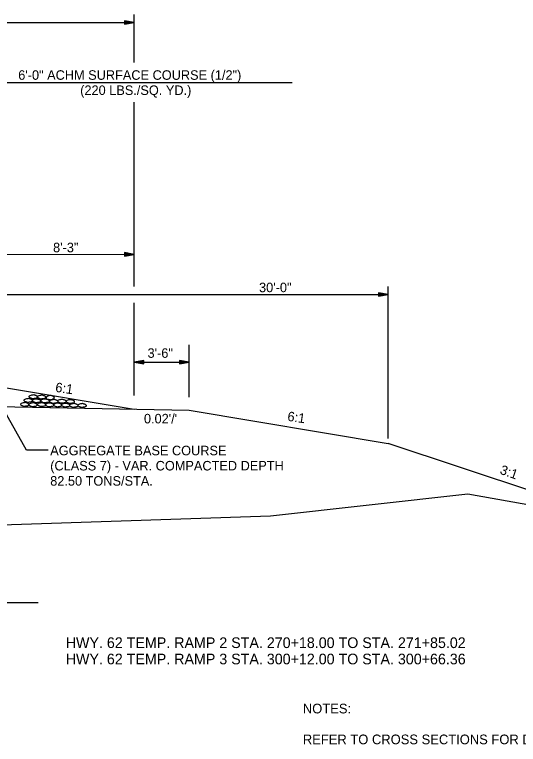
# Model space of a CAD drawing. Extents: x 1734743 to 1735935, y 759845 to 763831.
# Drawn here: x 1735771.91 to 1735803.12, y 759894.89 to 759940.09 of the extents above; entities that cross this region are included whole.
import ezdxf

# ---------------------------------------------------------------- set-up
doc = ezdxf.new("R2010")
doc.units = 0
for name, color, linetype in [('1', 7, 'Continuous'), ('19', 7, 'Continuous'), ('Level 1', 7, 'Continuous')]:
    doc.layers.add(name, color=color, linetype=linetype)

# ---------------------------------------------------------------- blocks, each defined once
blk = doc.blocks.new('ROCKS')
at = {"layer": '1'}
blk.add_spline([(0.013, 0.06), (0.053, 0.053), (0.107, 0.033), (0.133, 0.013), (0.133, -0.007), (0.12, -0.033), (0.107, -0.04), (0.073, -0.053), (0.033, -0.067), (0.013, -0.067), (-0.02, -0.06), (-0.06, -0.053), (-0.087, -0.047), (-0.113, -0.02), (-0.113, -0.007), (-0.107, 0.02), (-0.087, 0.033), (-0.067, 0.047), (-0.033, 0.053), (-0.02, 0.06), (0.013, 0.06)], degree=3, dxfattribs=at)

msp = doc.modelspace()

# ---------------------------------------------------------------- linework, layer by layer
at = {"layer": '19'}
for p, q in [((1735779.325, 759937.131), (1735779.325, 759940.095)), ((1735737.495, 759939.61), (1735779.325, 759939.61)), ((1735778.725, 759939.715), (1735778.725, 759939.505)), ((1735779.325, 759939.61), (1735778.725, 759939.715)), ((1735779.165, 759939.625), (1735778.725, 759939.66)), ((1735778.725, 759939.505), (1735779.325, 759939.61)), ((1735778.725, 759939.555), (1735779.165, 759939.595)), ((1735765.047, 759935.882), (1735789.111, 759935.882)), ((1735779.325, 759925.787), (1735779.325, 759934.676)), ((1735779.324, 759923.251), (1735779.325, 759925.787)), ((1735778.725, 759925.35), (1735778.725, 759925.14)), ((1735779.325, 759925.245), (1735778.725, 759925.35)), ((1735779.165, 759925.26), (1735778.725, 759925.295)), ((1735771.047, 759925.246), (1735779.325, 759925.245)), ((1735778.725, 759925.14), (1735779.325, 759925.245)), ((1735778.725, 759925.19), (1735779.165, 759925.23)), ((1735795.046, 759913.832), (1735795.046, 759923.252)), ((1735765.047, 759922.754), (1735795.046, 759922.754)), ((1735794.446, 759922.859), (1735794.446, 759922.649)), ((1735795.046, 759922.754), (1735794.446, 759922.859)), ((1735794.886, 759922.769), (1735794.446, 759922.804)), ((1735794.446, 759922.649), (1735795.046, 759922.754)), ((1735794.446, 759922.699), (1735794.886, 759922.739)), ((1735779.325, 759916.499), (1735779.325, 759922.252)), ((1735782.727, 759916.396), (1735782.727, 759919.643)), ((1735779.925, 759918.667), (1735779.325, 759918.562)), ((1735779.325, 759918.562), (1735782.727, 759918.562)), ((1735779.325, 759918.562), (1735779.925, 759918.457)), ((1735779.925, 759918.612), (1735779.485, 759918.577)), ((1735779.485, 759918.547), (1735779.925, 759918.507)), ((1735779.925, 759918.457), (1735779.925, 759918.667)), ((1735782.126, 759918.667), (1735782.126, 759918.457)), ((1735782.726, 759918.562), (1735782.126, 759918.667)), ((1735782.566, 759918.577), (1735782.126, 759918.612)), ((1735782.126, 759918.457), (1735782.726, 759918.562)), ((1735782.126, 759918.507), (1735782.566, 759918.547)), ((1735771.048, 759917.035), (1735779.325, 759915.655)), ((1735772.655, 759913.11), (1735770.742, 759916.503)), ((1735767.034, 759915.902), (1735782.728, 759915.586)), ((1735767.035, 759915.902), (1735782.727, 759915.587)), ((1735782.727, 759915.587), (1735795.046, 759913.532)), ((1735809.505, 759908.711), (1735795.046, 759913.532)), ((1735773.986, 759913.11), (1735772.655, 759913.11)), ((1735745.216, 759903.685), (1735773.379, 759903.682))]:
    msp.add_line(p, q, dxfattribs=at)
msp.add_lwpolyline([(1735737.574, 759909.405), (1735737.825, 759909.397), (1735746.995, 759910.076), (1735752.775, 759907.356), (1735767.375, 759908.375), (1735787.755, 759909.053), (1735799.985, 759910.412), (1735809.495, 759908.711), (1735820.81, 759911.149), (1735822.413, 759910.838)], dxfattribs=at)

# ---------------------------------------------------------------- block references
at = {"layer": 'Level 1'}
for p, xscale, yscale, rotation in [((1735772.773, 759916.204), 2.011654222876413, -2.011654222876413, 178.17361855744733), ((1735773.086, 759916.429), 2.011654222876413, -2.011654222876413, 178.17361855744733), ((1735773.291, 759916.181), 2.011654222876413, -2.011654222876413, 178.17361855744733), ((1735773.6, 759916.415), 2.011654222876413, -2.011654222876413, 178.17361855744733), ((1735773.82, 759916.177), 2.011654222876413, -2.011654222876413, 178.17361855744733), ((1735774.104, 759916.378), 2.0116542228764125, 2.0116542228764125, 0.9122903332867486), ((1735774.356, 759916.145), 2.011654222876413, -2.011654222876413, 178.17361855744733), ((1735774.862, 759916.152), 2.011654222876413, -2.011654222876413, 178.17361855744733), ((1735775.383, 759916.137), 2.011654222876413, -2.011654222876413, 178.17361855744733), ((1735772.557, 759915.955), 2.011654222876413, -2.011654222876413, 178.17361855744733), ((1735773.072, 759915.937), 2.011654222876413, -2.011654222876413, 178.17361855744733), ((1735773.611, 759915.946), 2.011654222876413, -2.011654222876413, 178.17361855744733), ((1735774.101, 759915.93), 2.011654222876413, -2.011654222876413, 178.17361855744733), ((1735774.598, 759915.923), 2.011654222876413, -2.011654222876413, 178.17361855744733), ((1735775.094, 759915.912), 2.011654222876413, -2.011654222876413, 178.17361855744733), ((1735775.594, 759915.898), 2.011654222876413, -2.011654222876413, 178.17361855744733), ((1735776.115, 759915.892), 2.011654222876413, -2.011654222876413, 178.17361855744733)]:
    msp.add_blockref('ROCKS', p, dxfattribs=dict(at, xscale=xscale, yscale=yscale, rotation=rotation))

# ---------------------------------------------------------------- texts
at = {"layer": '1'}
for s, p in [('NOTES:', (1735789.766, 759896.812)), ('REFER TO CROSS SECTIONS FOR DEVIATION FROM NORMAL SLOPES. NO CHANGES', (1735789.766, 759894.901))]:
    msp.add_text(s, height=0.6, dxfattribs=at).set_placement(p)
at = {"layer": '19'}
for s, height, rotation, p in [('6\'-0" ACHM SURFACE COURSE (1/2")', 0.59001, 359.9954, (1735772.137, 759936.057)), ('(220 LBS./SQ. YD.)', 0.59001, 359.9954, (1735775.975, 759935.117)), ('8\'-3"', 0.59, 359.9954, (1735774.295, 759925.374)), ('30\'-0"', 0.59, 359.9954, (1735787.053, 759922.901)), ('3\'-6"', 0.59, 359.9954, (1735780.146, 759918.836)), ('6:1', 0.59, 351.855, (1735774.407, 759916.732)), ("0.02'/'", 0.59, 359.9954, (1735779.924, 759914.774)), ('6:1', 0.59, 351.855, (1735788.783, 759914.936)), ('AGGREGATE BASE COURSE', 0.59001, 360, (1735774.118, 759912.799)), ('(CLASS 7) - VAR. COMPACTED DEPTH', 0.59001, 360, (1735774.118, 759911.859)), ('3:1', 0.59, 340.4896, (1735801.927, 759911.663)), ('82.50 TONS/STA.', 0.59001, 360, (1735774.118, 759910.919)), ('HWY. 62 TEMP. RAMP 2 STA. 270+18.00 TO STA. 271+85.02', 0.65999, 359.9954, (1735775.079, 759900.862)), ('HWY. 62 TEMP. RAMP 3 STA. 300+12.00 TO STA. 300+66.36', 0.65999, 359.9954, (1735775.078, 759899.852))]:
    msp.add_text(s, height=height, rotation=rotation, dxfattribs=at).set_placement(p)

doc.saveas('drawing.dxf')
